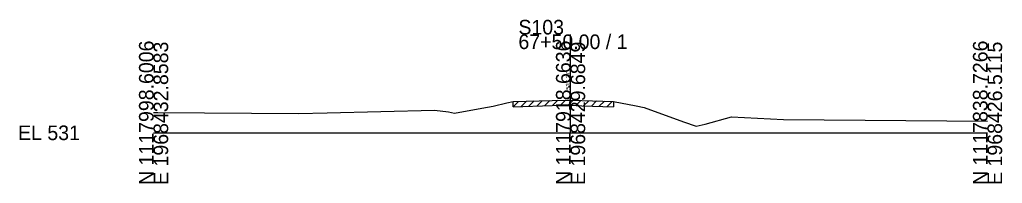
# Model space of a CAD drawing. Extents: x -26 to 163, y -10 to 45020.
# Drawn here: x -25.7 to 162.8, y 26490.3 to 26521.7 of the extents above; entities that cross this region are included whole.
import ezdxf

# ---------------------------------------------------------------- set-up
doc = ezdxf.new("R2010")
doc.units = 0
for name, color, linetype in [('RD_GPK_XS_Cell', 7, 'Continuous'), ('RD_XS_ExGround', 7, 'Continuous'), ('RD_XS_ExPaveRet', 7, 'Continuous'), ('RD_XS_TX_Elev_EX', 7, 'Continuous')]:
    doc.layers.add(name, color=color, linetype=linetype)

msp = doc.modelspace()

# ---------------------------------------------------------------- linework, layer by layer
at = {"layer": 'RD_GPK_XS_Cell'}
for p, q in [((80, 26500), (80, 26518.86)), ((0, 26500), (80, 26500)), ((80, 26500), (160, 26500))]:
    msp.add_line(p, q, dxfattribs=at)
at = {"layer": 'RD_XS_ExGround'}
for p, q in [((67.77, 26505.74), (69.01, 26506)), ((69.01, 26506), (76.47, 26506.21)), ((76.47, 26506.21), (79.48, 26506.29)), ((79.48, 26506.29), (80, 26506.27)), ((80, 26506.27), (82.15, 26506.2)), ((82.15, 26506.2), (88.24, 26506)), ((88.24, 26506), (92.58, 26505.16)), ((33.3, 26503.85), (53.92, 26504.35)), ((53.92, 26504.35), (56.59, 26503.99)), ((56.59, 26503.99), (57.74, 26503.78)), ((57.74, 26503.78), (63, 26504.72)), ((63, 26504.72), (65.13, 26505.12)), ((65.13, 26505.12), (67.77, 26505.74)), ((92.58, 26505.16), (94.14, 26504.87)), ((94.14, 26504.87), (101.7, 26502.09)), ((0, 26503.89), (0.81, 26503.9)), ((0.81, 26503.9), (27.77, 26503.72)), ((27.77, 26503.72), (33.3, 26503.85)), ((101.7, 26502.09), (104.13, 26501.28)), ((105.81, 26501.64), (110.87, 26503.09)), ((110.87, 26503.09), (120.83, 26502.55)), ((120.83, 26502.55), (160, 26502.22)), ((104.13, 26501.28), (105.81, 26501.64))]:
    msp.add_line(p, q, dxfattribs=at)
at = {"layer": 'RD_XS_ExPaveRet'}
for p, q in [((69.01, 26505), (70.04, 26506.03)), ((69.01, 26505), (69.01, 26506)), ((70.51, 26505.04), (71.54, 26506.07)), ((72.01, 26505.08), (73.04, 26506.11)), ((73.51, 26505.12), (74.54, 26506.15)), ((75.01, 26505.17), (76.04, 26506.2)), ((76.51, 26505.21), (77.54, 26506.24)), ((78.01, 26505.25), (79.04, 26506.27)), ((79.51, 26505.28), (80.48, 26506.25)), ((81.01, 26505.24), (81.98, 26506.2)), ((82.51, 26505.19), (83.48, 26506.16)), ((84.01, 26505.14), (84.98, 26506.11)), ((85.51, 26505.09), (86.48, 26506.06)), ((87.01, 26505.04), (87.98, 26506.01)), ((88.24, 26506), (88.24, 26505)), ((69.01, 26505), (76.47, 26505.21)), ((76.47, 26505.21), (79.48, 26505.29)), ((79.48, 26505.29), (80, 26505.27)), ((80, 26505.27), (82.15, 26505.2)), ((82.15, 26505.2), (88.24, 26505))]:
    msp.add_line(p, q, dxfattribs=at)

# ---------------------------------------------------------------- texts
at = {"layer": 'RD_GPK_XS_Cell'}
for s, p in [('S103', (70, 26518.86)), ('67+50.00 / 1', (70, 26516.06)), ('EL 531', (-26, 26498.6))]:
    msp.add_text(s, height=2.8, dxfattribs=at).set_placement(p)
for s, p in [('N 1117998.6006', (0, 26490)), ('E 1968432.8583', (2.8, 26490)), ('N 1117918.6636', (80, 26490)), ('E 1968429.6849', (82.8, 26490)), ('N 1117838.7266', (160, 26490)), ('E 1968426.5115', (162.8, 26490))]:
    msp.add_text(s, height=2.8, rotation=90, dxfattribs=at).set_placement(p)
at = {"layer": 'RD_XS_TX_Elev_EX'}
msp.add_text('537.27', height=0.8, rotation=90, dxfattribs=at).set_placement((79.9, 26508.27))

doc.saveas('drawing.dxf')
